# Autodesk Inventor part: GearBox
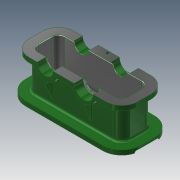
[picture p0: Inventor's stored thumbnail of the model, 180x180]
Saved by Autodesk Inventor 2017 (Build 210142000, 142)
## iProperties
Created: 2016-10
Part Number: GearBox
Material: Generic
Document SubType Name: Modeling
Designer: Drago Šandor
Density: 1 g/cm^3
Appearance: Smooth - Dark Forest Green
Author: Drago Šandor
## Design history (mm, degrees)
sketch "Sketch1"
  geometry: L1 (0, -147)-(0, 147) reference; L2 (-49, 0)-(49, 0) reference; L3 (35, 105)-(-35, 105); L4 (-35, 105)-(-35, -105); L5 (-35, -105)-(35, -105); L6 (35, -105)-(35, 105); 3 further points
  constraints: 8 end point, 2 midpoint, 2 parallel, 2 point on line, 1 horizontal, 1 perpendicular
  dimensions: "d0" = 70 distance of L4.end L5.end; "d1" = 210 distance of L5.end L3.start
extrude "Extrusion1" new body sketch "Sketch1" distance "d2" = 90; taper "d3" = 0 deg
fillet "Fillet1" dims "d4" = 20
shell "Shell1" dims "d5" = 6
fillet "Fillet2" dims "d6" = 20
sketch "Sketch2"
  geometry: L1 (-15, -105)-(15, -105) reference; L2 (-35, 85)-(-35, -85) reference; L3 (15, 105)-(-15, 105) reference; L4 (35, -85)-(35, 85) reference; L5 (-15, -127)-(15, -127); L6 (57, -85)-(57, 85); L7 (15, 127)-(-15, 127); L8 (-57, 85)-(-57, -85); A1 r 20 centre (-15, -85) between (-35, -85) and (-15, -105) reference; A2 r 20 centre (-15, 85) between (-15, 105) and (-35, 85) reference; A3 r 20 centre (15, 85) between (35, 85) and (15, 105) reference; A4 r 20 centre (15, -85) between (15, -105) and (35, -85) reference; A5 r 42 centre (-15, -85) between (-57, -85) and (-15, -127); A6 r 42 centre (15, -85) between (15, -127) and (57, -85); A7 r 42 centre (15, 85) between (57, 85) and (15, 127); A8 r 42 centre (-15, 85) between (-15, 127) and (-57, 85); 1 further point
  constraints: 8 end point, 8 point on circle, 4 centre point
  dimensions: "d7" = 22 distance between parallel lines of L2 L8
extrude "Extrusion2" join sketch "Sketch2" distance "d8" = 10; taper "d9" = 0 deg
sketch "Sketch3"
  geometry: L1 (35, -85)-(35, 85) reference; L2 (-15, -105)-(15, -105) reference; L3 (-35, 85)-(-35, -85) reference; L4 (15, 105)-(-15, 105) reference; L5 (15, 120)-(-15, 120); L6 (-50, 85)-(-50, -85); L7 (-15, -120)-(15, -120); L8 (50, -85)-(50, 85); A1 r 20 centre (15, 85) between (35, 85) and (15, 105) reference; A2 r 20 centre (15, -85) between (15, -105) and (35, -85) reference; A3 r 20 centre (-15, -85) between (-35, -85) and (-15, -105) reference; A4 r 20 centre (-15, 85) between (-15, 105) and (-35, 85) reference; A5 r 35 centre (15, 85) between (50, 85) and (15, 120); A6 r 35 centre (-15, 85) between (-15, 120) and (-50, 85); A7 r 35 centre (-15, -85) between (-50, -85) and (-15, -120); A8 r 35 centre (15, -85) between (15, -120) and (50, -85); 1 further point
  constraints: 8 end point, 8 point on circle, 4 centre point
  dimensions: "d10" = 15 distance between parallel lines of L1 L8
extrude "Extrusion3" join sketch "Sketch3" distance "d11" = 10; taper "d12" = 0 deg
sketch "Sketch4"
  geometry: L1 (30, 0)-(0, 0) reference; L2 (-12, 0)-(42, 0); L3 (42, 0)-(42, 5); L4 (42, 5)-(-12, 5); L5 (-12, 5)-(-12, 0); L6 (-42, 0)-(-42, 10) reference; L7 (72, 0)-(72, 10) reference; 1 further point
  constraints: 8 end point, 2 parallel, 1 horizontal, 1 perpendicular, 1 point on line
  dimensions: "d13" = 5 distance of L2.end L3.end; "d14" = 30 distance between parallel lines of L5 L6; "d15" = 30 distance between parallel lines of L7 L3
extrude "Extrusion4" cut sketch "Sketch4" stored distance "d16" = 10; taper "d17" = 0 deg
fillet "Fillet3" dims "d18" = 5
fillet "Fillet4" dims "d19" = 5
chamfer "Chamfer1" distance "d20" = 1; stored, may be unused: second distance "d21" = 2, angle "d22" = 45 deg
sketch "Sketch5"
  geometry: L1 (0, 0)-(170, 0) reference; L2 (184, -64)-(184, -1) reference; L3 (205, 0)-(170, 0) reference; L4 (170, -1)-(184, -1) reference; L5 (0, 0)-(170, 0) reference; L6 (21.5, 0)-(76.5, 0); L7 (106.5, 0)-(161.5, 0); A1 r 27.5 centre (49, 0) between (21.5, 0) and (76.5, 0); A2 r 27.5 centre (134, 0) between (106.5, 0) and (161.5, 0); 2 further points
  constraints: 6 point on line, 4 end point, 4 point on circle, 2 centre point, 2 collinear, 1 coincident
  dimensions: "d23" = 55 diameter of A1; "d24" = 55 diameter of A2; "d25" = 50 horizontal distance of A2.centre point (184, -1); "d26" = 85 distance of A1.centre A2.centre
extrude "Extrusion5" join sketch "Sketch5" stored distance "d27" = 10; taper "d28" = 0 deg
sketch "Sketch6"
  geometry: C1 r 17.5 at (49, 0); C2 r 18.5 at (134, 0); A1 r 27.5 centre (49, 0) between (23.383, -10) and (74.617, -10) reference; A2 r 27.5 centre (134, 0) between (108.383, -10) and (159.617, -10) reference; 1 further point
  constraints: 2 centre point, 2 coincident
  dimensions: "d29" = 35 diameter of C1; "d30" = 37 diameter of C2
extrude "Extrusion6" cut sketch "Sketch6" distance "d31" = 19; taper "d32" = 0 deg
sketch "Sketch7"
  geometry: L1 (34, 0)-(64, 0); L2 (0, 0)-(170, 0) reference; L3 (118, 0)-(150, 0); A1 r 17.5 centre (49, 0) between (31.5, 0) and (66.5, 0) reference; A2 r 18.5 centre (134, 0) between (115.5, 0) and (152.5, 0) reference; A3 r 15 centre (49, 0) between (34, 0) and (64, 0); A4 r 16 centre (134, 0) between (118, 0) and (150, 0); 1 further point
  constraints: 4 end point, 4 point on circle, 2 centre point, 2 collinear
  dimensions: "d33" = 2.5 radial gap between concentric circles of A1 A3; "d34" = 2.5 radial gap between concentric circles of A2 A4
extrude "Extrusion7" cut sketch "Sketch7" stored distance "d35" = 19; taper "d36" = 0 deg
workaxis "Work Axis1"
workaxis "Work Axis2"
workplane "Work Plane1"
workplane "Work Plane2"
sketch "Sketch8"
  geometry: L1 (0, 10)-(0, 27.5) reference; L2 (0, 27.5)-(0, 32.5); L3 (0, 27.5)-(15, 27.5) reference; L4 (15, 75)-(15, 10) reference; L5 (0, 32.5)-(15, 67.5); L6 (15, 27.5)-(15, 67.5); L7 (15, 10)-(15, 75) reference; L8 (15, 27.5)-(0, 27.5); 1 further point
  constraints: 8 end point, 2 collinear, 1 point on line, 1 vertical
  dimensions: "d39" = 5 distance of L1.end L2.end; "d40" = 35 vertical distance of L5.end L2.end
feature "Rib1" sketch "Sketch8" dims "d41" = 1, "d42" = 5, "d43" = 0, "d44" = 0, "d45" = 1, "d46" = 1
sketch "Sketch10"
  geometry: L1 (0, 27.5)-(15, 27.5) reference; L2 (15, 10)-(15, 75) reference; L3 (0, 27.5)-(0, 32.5); L4 (0, 32.5)-(15, 67.5); 1 further point
  constraints: 4 end point, 1 point on line, 1 vertical
  dimensions: "d47" = 5 distance of L1.start L3.end; "d48" = 35 vertical distance of L4.end L3.end
feature "Rib2" sketch "Sketch10" dims "d49" = 1, "d50" = 5, "d51" = 0, "d52" = 0, "d53" = 1, "d54" = 1
fillet "Fillet5" dims "d55" = 2
workplane "Work Plane3"
mirror "Mirror1"
fillet "Fillet6" dims "d56" = 5
fillet "Fillet7" dims "d57" = 2
sketch "Sketch11"
  geometry: L1 (150, 10)-(170, 10) reference; L2 (152.5, 10)-(151.5, 10); L3 (116.5, 10)-(115.5, 10); A1 r 18.5 centre (134, 10) between (115.5, 10) and (152.5, 10) reference; A2 r 17.5 centre (134, 10) between (116.5, 10) and (151.5, 10); A3 r 18.5 centre (134, 10) between (115.5, 10) and (152.5, 10); 2 further points
  constraints: 4 end point, 4 point on circle, 2 centre point, 2 coincident
  dimensions: "d58" = 35 diameter of A2
extrude "Extrusion8" join sketch "Sketch11" stored distance "d59" = 10; taper "d60" = 0 deg
sketch "Sketch12"
  geometry: C1 r 21 at (49, 10); A1 r 17.5 centre (49, 10) between (31.5, 10) and (66.5, 10) reference; 1 further point
  constraints: 1 centre point, 1 coincident
  dimensions: "d61" = 42 diameter of C1
extrude "Extrusion9" cut sketch "Sketch12" stored distance "d62" = 10; taper "d63" = 0 deg
mirror "Mirror2"
sketch "Sketch13"
  geometry: L1 (57, -85)-(57, 85) reference; L2 (40, 23.383)-(50, 23.383) reference; L3 (35.162, -36.5)-(50, -36.5) reference; L4 (50, -10.383)-(40, -10.383) reference; 2 further points
  dimensions: "d64" = 12 distance from line of L1 point (45, 6.617); "d68" = 17 distance from line of L4 point (45, 6.617)
hole "Hole1" sketch "Sketch13" at (45, 6.617) diameter "d69" = 5; stored, may be unused: countersink angle "d73" = 90 deg, drill point angle "d75" = 118 deg; dims "d70" = 6, "d71" = 4, "d72" = 2, "d74" = 8
sketch "Sketch14"
  geometry: L1 (52, 10)-(54.5, 10) reference; L2 (53.5, 10)-(54.5, 10); L3 (18.5, 10)-(17.5, 10); L4 (0, 10)-(20, 10) reference; A1 r 18.5 centre (36, 10) between (17.5, 10) and (54.5, 10) reference; A2 r 18.5 centre (36, 10) between (17.5, 10) and (54.5, 10); A3 r 17.5 centre (36, 10) between (18.5, 10) and (53.5, 10) reference; A4 r 17.5 centre (36, 10) between (53.5, 10) and (53.5, 10); 1 further point
  constraints: 4 end point, 4 point on circle, 2 centre point, 2 coincident, 2 collinear
  dimensions: "d76" = 17.5 radius of A4 (derived)
extrude "Extrusion10" join sketch "Sketch14" stored distance "d77" = 10; taper "d78" = 0 deg
body "Solid1"
other parameters: "d37" = 0, "d38" = 0
